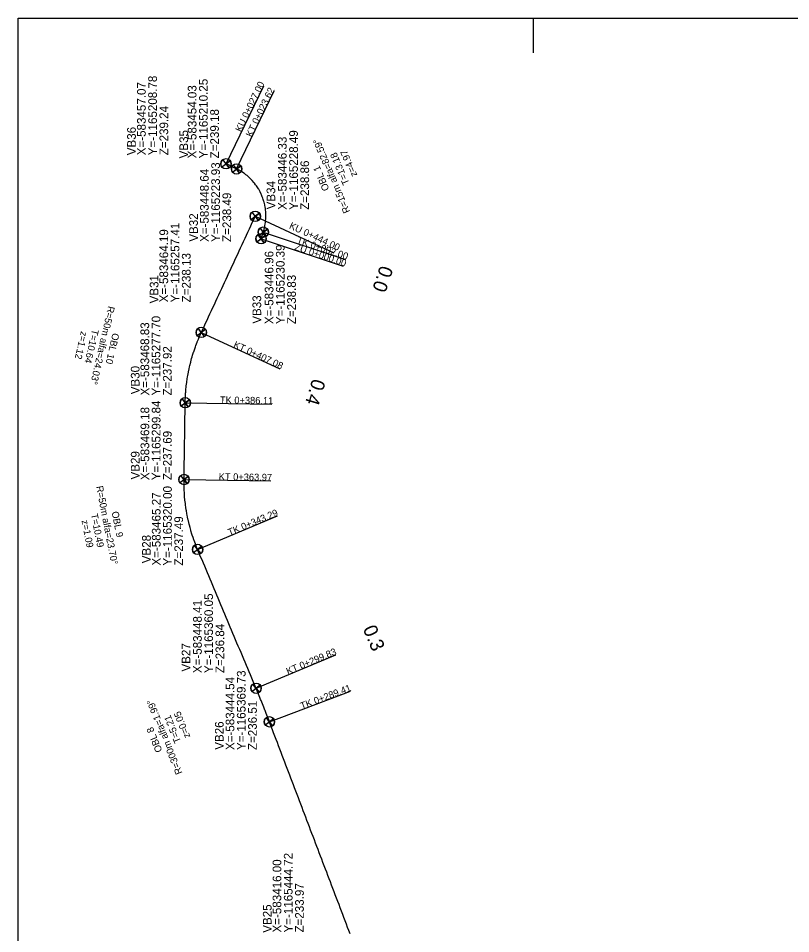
# Model space of a CAD drawing. Extents: x -583517 to -548566, y -1166112 to -1101582.
# Drawn here: x -583517 to -583294.2, y -1165430.8 to -1165166.8 of the extents above; entities that cross this region are included whole.
import ezdxf

# ---------------------------------------------------------------- set-up
doc = ezdxf.new("R2010")
doc.units = 0
for name, color, linetype in [('13', 7, 'Continuous'), ('56', 7, 'Continuous'), ('59', 7, 'Continuous'), ('8', 7, 'Continuous'), ('Body pricny rez', 7, 'Continuous'), ('Popis pricneho profilu', 7, 'Continuous')]:
    doc.layers.add(name, color=color, linetype=linetype)

msp = doc.modelspace()

# ---------------------------------------------------------------- linework, layer by layer
at = {"layer": '13'}
for points in [[(-583457.07, -1165208.78), (-583446.19, -1165186.27)], [(-583454.03, -1165210.25), (-583443.15, -1165187.75)], [(-583448.64, -1165223.93), (-583425.96, -1165234.46)], [(-583446.33, -1165228.49), (-583422.61, -1165236.38)], [(-583446.96, -1165230.39), (-583423.24, -1165238.28)], [(-583464.19, -1165257.41), (-583441.51, -1165267.94)], [(-583468.83, -1165277.7), (-583443.84, -1165278.09)], [(-583469.18, -1165299.84), (-583444.18, -1165300.22)], [(-583465.27, -1165320), (-583442.22, -1165310.3)], [(-583448.41, -1165360.05), (-583425.37, -1165350.36)], [(-583444.54, -1165369.73), (-583421.17, -1165360.84)]]:
    msp.add_lwpolyline(points, dxfattribs=at)
at = {"layer": '56'}
msp.add_lwpolyline([(-583446.96, -1165230.39), (-583446.65, -1165229.44), (-583446.33, -1165228.49), (-583446.1, -1165227.72), (-583446.05, -1165227.53), (-583445.91, -1165226.95), (-583445.83, -1165226.56), (-583445.76, -1165226.16), (-583445.68, -1165225.57), (-583445.65, -1165225.37), (-583445.59, -1165224.57), (-583445.59, -1165224.57), (-583445.57, -1165223.77), (-583445.57, -1165223.57), (-583445.59, -1165222.97), (-583445.61, -1165222.57), (-583445.65, -1165222.17), (-583445.72, -1165221.58), (-583445.76, -1165221.38), (-583445.9, -1165220.6), (-583445.9, -1165220.59), (-583446.09, -1165219.81), (-583446.14, -1165219.63), (-583446.32, -1165219.04), (-583446.45, -1165218.67), (-583446.6, -1165218.29), (-583446.82, -1165217.75), (-583446.91, -1165217.55), (-583447.25, -1165216.84), (-583447.26, -1165216.83), (-583447.65, -1165216.13), (-583447.74, -1165215.97), (-583448.07, -1165215.45), (-583448.29, -1165215.14), (-583448.53, -1165214.8), (-583448.89, -1165214.34), (-583449.03, -1165214.17), (-583449.54, -1165213.58), (-583449.56, -1165213.57), (-583450.11, -1165212.99), (-583450.25, -1165212.87), (-583450.7, -1165212.45), (-583450.99, -1165212.2), (-583451.32, -1165211.94), (-583451.78, -1165211.59), (-583451.96, -1165211.47), (-583452.61, -1165211.03), (-583452.63, -1165211.02), (-583453.32, -1165210.62), (-583453.48, -1165210.53), (-583454.03, -1165210.25), (-583454.37, -1165210.09), (-583455.27, -1165209.65), (-583456.17, -1165209.22), (-583457.07, -1165208.78)], dxfattribs=at)
at = {"layer": '8'}
for p, q in [((-583458.28, -1165209.67), (-583455.87, -1165207.89)), ((-583456.18, -1165209.98), (-583457.97, -1165207.58)), ((-583457.07, -1165208.78), (-583457.97, -1165207.58)), ((-583455.87, -1165207.88), (-583457.07, -1165208.78)), ((-583455.87, -1165207.88), (-583457.07, -1165208.78)), ((-583458.28, -1165209.68), (-583457.07, -1165208.78)), ((-583457.07, -1165208.78), (-583456.18, -1165209.98)), ((-583457.07, -1165208.78), (-583456.18, -1165209.98)), ((-583455.24, -1165211.15), (-583452.83, -1165209.36)), ((-583455.24, -1165211.15), (-583454.03, -1165210.25)), ((-583453.14, -1165211.45), (-583454.93, -1165209.05)), ((-583454.03, -1165210.25), (-583454.93, -1165209.05)), ((-583452.83, -1165209.36), (-583454.03, -1165210.25)), ((-583452.83, -1165209.36), (-583454.03, -1165210.25)), ((-583454.03, -1165210.25), (-583453.14, -1165211.45)), ((-583454.03, -1165210.25), (-583453.14, -1165211.45)), ((-583449.84, -1165224.82), (-583447.43, -1165223.03)), ((-583449.84, -1165224.82), (-583448.64, -1165223.93)), ((-583447.74, -1165225.13), (-583449.53, -1165222.72)), ((-583448.64, -1165223.93), (-583449.53, -1165222.72)), ((-583447.43, -1165223.03), (-583448.64, -1165223.93)), ((-583447.43, -1165223.03), (-583448.64, -1165223.93)), ((-583448.64, -1165223.93), (-583447.74, -1165225.13)), ((-583448.64, -1165223.93), (-583447.74, -1165225.13)), ((-583448.17, -1165231.28), (-583445.76, -1165229.49)), ((-583446.07, -1165231.59), (-583447.86, -1165229.18)), ((-583446.96, -1165230.39), (-583447.86, -1165229.18)), ((-583447.54, -1165229.38), (-583445.13, -1165227.6)), ((-583447.54, -1165229.39), (-583446.33, -1165228.49)), ((-583445.44, -1165229.69), (-583447.23, -1165227.29)), ((-583446.33, -1165228.49), (-583447.23, -1165227.29)), ((-583445.76, -1165229.49), (-583446.96, -1165230.39)), ((-583445.76, -1165229.49), (-583446.96, -1165230.39)), ((-583445.13, -1165227.59), (-583446.33, -1165228.49)), ((-583445.13, -1165227.59), (-583446.33, -1165228.49)), ((-583446.33, -1165228.49), (-583445.44, -1165229.69)), ((-583446.33, -1165228.49), (-583445.44, -1165229.69)), ((-583448.17, -1165231.28), (-583446.96, -1165230.39)), ((-583446.96, -1165230.39), (-583446.07, -1165231.59)), ((-583446.96, -1165230.39), (-583446.07, -1165231.59)), ((-583465.39, -1165258.31), (-583462.98, -1165256.52)), ((-583465.39, -1165258.31), (-583464.19, -1165257.41)), ((-583463.29, -1165258.62), (-583465.08, -1165256.21)), ((-583464.19, -1165257.41), (-583465.08, -1165256.21)), ((-583462.98, -1165256.52), (-583464.19, -1165257.41)), ((-583462.98, -1165256.52), (-583464.19, -1165257.41)), ((-583464.19, -1165257.41), (-583463.29, -1165258.62)), ((-583464.19, -1165257.41), (-583463.29, -1165258.62)), ((-583470.04, -1165278.6), (-583467.63, -1165276.81)), ((-583467.94, -1165278.91), (-583469.73, -1165276.5)), ((-583468.83, -1165277.7), (-583469.73, -1165276.5)), ((-583467.63, -1165276.81), (-583468.83, -1165277.7)), ((-583467.63, -1165276.81), (-583468.83, -1165277.7)), ((-583470.04, -1165278.6), (-583468.83, -1165277.7)), ((-583468.83, -1165277.7), (-583467.94, -1165278.91)), ((-583468.83, -1165277.7), (-583467.94, -1165278.91)), ((-583470.38, -1165300.73), (-583467.97, -1165298.94)), ((-583470.38, -1165300.73), (-583469.18, -1165299.84)), ((-583468.28, -1165301.04), (-583470.07, -1165298.63)), ((-583469.18, -1165299.84), (-583470.07, -1165298.63)), ((-583467.97, -1165298.94), (-583469.18, -1165299.84)), ((-583467.97, -1165298.94), (-583469.18, -1165299.84)), ((-583469.18, -1165299.84), (-583468.28, -1165301.04)), ((-583469.18, -1165299.84), (-583468.28, -1165301.04)), ((-583466.47, -1165320.89), (-583464.06, -1165319.1)), ((-583464.37, -1165321.2), (-583466.16, -1165318.8)), ((-583465.27, -1165320), (-583466.16, -1165318.8)), ((-583464.06, -1165319.1), (-583465.27, -1165320)), ((-583464.06, -1165319.1), (-583465.27, -1165320)), ((-583466.47, -1165320.89), (-583465.27, -1165320)), ((-583465.27, -1165320), (-583464.37, -1165321.2)), ((-583465.27, -1165320), (-583464.37, -1165321.2)), ((-583447.52, -1165361.26), (-583449.31, -1165358.85)), ((-583448.41, -1165360.05), (-583449.31, -1165358.85)), ((-583449.62, -1165360.95), (-583447.21, -1165359.16)), ((-583449.62, -1165360.95), (-583448.41, -1165360.05)), ((-583447.21, -1165359.16), (-583448.41, -1165360.05)), ((-583447.21, -1165359.16), (-583448.41, -1165360.05)), ((-583448.41, -1165360.05), (-583447.52, -1165361.26)), ((-583448.41, -1165360.05), (-583447.52, -1165361.26)), ((-583445.74, -1165370.63), (-583443.33, -1165368.84)), ((-583443.64, -1165370.93), (-583445.43, -1165368.53)), ((-583444.54, -1165369.73), (-583445.43, -1165368.53)), ((-583443.33, -1165368.84), (-583444.54, -1165369.73)), ((-583443.33, -1165368.84), (-583444.54, -1165369.73)), ((-583445.74, -1165370.63), (-583444.54, -1165369.73)), ((-583444.54, -1165369.73), (-583443.64, -1165370.94)), ((-583444.54, -1165369.73), (-583443.64, -1165370.94))]:
    msp.add_line(p, q, dxfattribs=at)
for centre in [(-583457.07, -1165208.78), (-583454.03, -1165210.25), (-583448.64, -1165223.93), (-583446.33, -1165228.49), (-583446.96, -1165230.39), (-583464.19, -1165257.41), (-583468.83, -1165277.7), (-583469.18, -1165299.84), (-583465.27, -1165320), (-583448.41, -1165360.05), (-583444.54, -1165369.73)]:
    msp.add_circle(centre, 1.5, dxfattribs=at)
for centre, start, end in [((-583457.07, -1165208.78), 126.6271, 216.6271), ((-583457.07, -1165208.78), 306.6271, 36.6271), ((-583457.07, -1165208.78), 306.6271, 36.6271), ((-583454.03, -1165210.25), 126.6271, 216.6271), ((-583454.03, -1165210.25), 306.6271, 36.6271), ((-583454.03, -1165210.25), 306.6271, 36.6271), ((-583448.64, -1165223.93), 126.6271, 216.6271), ((-583448.64, -1165223.93), 306.6271, 36.6271), ((-583448.64, -1165223.93), 306.6271, 36.6271), ((-583446.96, -1165230.39), 126.6271, 216.6271), ((-583446.33, -1165228.49), 126.6271, 216.6271), ((-583446.96, -1165230.39), 306.6271, 36.6271), ((-583446.96, -1165230.39), 306.6271, 36.6271), ((-583446.33, -1165228.49), 306.6271, 36.6271), ((-583446.33, -1165228.49), 306.6271, 36.6271), ((-583464.19, -1165257.41), 126.6271, 216.6271), ((-583464.19, -1165257.41), 306.6271, 36.6271), ((-583464.19, -1165257.41), 306.6271, 36.6271), ((-583468.83, -1165277.7), 126.6271, 216.6271), ((-583468.83, -1165277.7), 306.6271, 36.6271), ((-583468.83, -1165277.7), 306.6271, 36.6271), ((-583469.18, -1165299.84), 126.6271, 216.6271), ((-583469.18, -1165299.84), 306.6271, 36.6271), ((-583469.18, -1165299.84), 306.6271, 36.6271), ((-583465.27, -1165320), 126.6271, 216.6271), ((-583465.27, -1165320), 306.6271, 36.6271), ((-583465.27, -1165320), 306.6271, 36.6271), ((-583448.41, -1165360.05), 126.6271, 216.6271), ((-583448.41, -1165360.05), 306.6271, 36.6271), ((-583448.41, -1165360.05), 306.6271, 36.6271), ((-583444.54, -1165369.73), 126.6271, 216.6271), ((-583444.54, -1165369.73), 306.6271, 36.6271), ((-583444.54, -1165369.73), 306.6271, 36.6271)]:
    msp.add_arc(centre, 1.5, start, end, dxfattribs=at)
at = {"layer": 'Body pricny rez'}
msp.add_lwpolyline([(-583421.28, -1165430.86), (-583421.63, -1165429.93), (-583421.99, -1165428.99), (-583422.35, -1165428.06), (-583422.7, -1165427.12), (-583423.06, -1165426.19), (-583423.41, -1165425.25), (-583423.77, -1165424.32), (-583424.12, -1165423.38), (-583424.48, -1165422.45), (-583424.83, -1165421.52), (-583425.19, -1165420.58), (-583425.55, -1165419.65), (-583425.9, -1165418.71), (-583426.26, -1165417.78), (-583426.61, -1165416.84), (-583426.97, -1165415.91), (-583427.32, -1165414.97), (-583427.68, -1165414.04), (-583428.04, -1165413.1), (-583428.39, -1165412.17), (-583428.75, -1165411.23), (-583429.1, -1165410.3), (-583429.46, -1165409.37), (-583429.81, -1165408.43), (-583430.17, -1165407.5), (-583430.52, -1165406.56), (-583430.88, -1165405.63), (-583431.24, -1165404.69), (-583431.59, -1165403.76), (-583431.95, -1165402.82), (-583432.3, -1165401.89), (-583432.66, -1165400.95), (-583433.01, -1165400.02), (-583433.37, -1165399.08), (-583433.72, -1165398.15), (-583434.08, -1165397.21), (-583434.44, -1165396.28), (-583434.79, -1165395.35), (-583435.15, -1165394.41), (-583435.5, -1165393.48), (-583435.86, -1165392.54), (-583436.21, -1165391.61), (-583436.57, -1165390.67), (-583436.93, -1165389.74), (-583437.28, -1165388.8), (-583437.64, -1165387.87), (-583437.99, -1165386.93), (-583438.35, -1165386), (-583438.7, -1165385.06), (-583439.06, -1165384.13), (-583439.41, -1165383.2), (-583439.77, -1165382.26), (-583440.13, -1165381.33), (-583440.48, -1165380.39), (-583440.84, -1165379.46), (-583441.19, -1165378.52), (-583441.55, -1165377.59), (-583441.9, -1165376.65), (-583442.26, -1165375.72), (-583442.61, -1165374.78), (-583442.97, -1165373.85), (-583443.33, -1165372.91), (-583443.68, -1165371.98), (-583444.04, -1165371.04), (-583444.39, -1165370.11), (-583444.54, -1165369.73), (-583444.75, -1165369.18), (-583445.11, -1165368.24), (-583445.47, -1165367.31), (-583445.79, -1165366.49), (-583445.84, -1165366.38), (-583446.2, -1165365.45), (-583446.58, -1165364.52), (-583446.95, -1165363.59), (-583447.08, -1165363.26), (-583447.33, -1165362.67), (-583447.71, -1165361.74), (-583448.09, -1165360.82), (-583448.41, -1165360.05), (-583448.48, -1165359.9), (-583448.87, -1165358.98), (-583449.25, -1165358.05), (-583449.64, -1165357.13), (-583450.03, -1165356.21), (-583450.42, -1165355.29), (-583450.81, -1165354.37), (-583451.19, -1165353.45), (-583451.58, -1165352.52), (-583451.97, -1165351.6), (-583452.16, -1165351.14), (-583452.36, -1165350.68), (-583452.74, -1165349.76), (-583453.13, -1165348.84), (-583453.52, -1165347.92), (-583453.91, -1165346.99), (-583454.3, -1165346.07), (-583454.68, -1165345.15), (-583455.07, -1165344.23), (-583455.46, -1165343.31), (-583455.85, -1165342.39), (-583456.24, -1165341.46), (-583456.62, -1165340.54), (-583457.01, -1165339.62), (-583457.4, -1165338.7), (-583457.79, -1165337.78), (-583458.17, -1165336.85), (-583458.56, -1165335.93), (-583458.95, -1165335.01), (-583459.34, -1165334.09), (-583459.73, -1165333.17), (-583460.11, -1165332.25), (-583460.5, -1165331.32), (-583460.89, -1165330.4), (-583461.28, -1165329.48), (-583461.67, -1165328.56), (-583462.05, -1165327.64), (-583462.44, -1165326.72), (-583462.83, -1165325.79), (-583463.22, -1165324.87), (-583463.6, -1165323.95), (-583463.99, -1165323.03), (-583464.38, -1165322.11), (-583464.77, -1165321.19), (-583465.16, -1165320.26), (-583465.27, -1165320), (-583465.54, -1165319.34), (-583465.82, -1165318.63), (-583465.9, -1165318.41), (-583466.25, -1165317.47), (-583466.33, -1165317.24), (-583466.58, -1165316.53), (-583466.8, -1165315.84), (-583466.89, -1165315.58), (-583467.18, -1165314.62), (-583467.23, -1165314.43), (-583467.45, -1165313.66), (-583467.62, -1165313), (-583467.7, -1165312.69), (-583467.93, -1165311.72), (-583467.97, -1165311.57), (-583468.14, -1165310.74), (-583468.27, -1165310.12), (-583468.34, -1165309.76), (-583468.51, -1165308.77), (-583468.53, -1165308.67), (-583468.66, -1165307.78), (-583468.74, -1165307.2), (-583468.8, -1165306.79), (-583468.91, -1165305.8), (-583468.92, -1165305.74), (-583469.01, -1165304.8), (-583469.05, -1165304.27), (-583469.08, -1165303.81), (-583469.13, -1165302.81), (-583469.13, -1165302.79), (-583469.17, -1165301.81), (-583469.18, -1165301.31), (-583469.18, -1165300.81), (-583469.18, -1165299.84), (-583469.18, -1165299.81), (-583469.16, -1165298.81), (-583469.14, -1165297.81), (-583469.13, -1165296.81), (-583469.11, -1165295.81), (-583469.1, -1165294.81), (-583469.08, -1165293.81), (-583469.07, -1165292.81), (-583469.05, -1165291.81), (-583469.04, -1165290.81), (-583469.02, -1165289.81), (-583469.01, -1165288.81), (-583468.99, -1165287.81), (-583468.98, -1165286.81), (-583468.96, -1165285.81), (-583468.94, -1165284.81), (-583468.93, -1165283.81), (-583468.91, -1165282.81), (-583468.9, -1165281.81), (-583468.88, -1165280.81), (-583468.87, -1165279.81), (-583468.85, -1165278.81), (-583468.84, -1165277.81), (-583468.83, -1165277.7), (-583468.81, -1165276.81), (-583468.79, -1165276.21), (-583468.77, -1165275.81), (-583468.71, -1165274.81), (-583468.7, -1165274.71), (-583468.62, -1165273.82), (-583468.56, -1165273.22), (-583468.52, -1165272.82), (-583468.4, -1165271.83), (-583468.38, -1165271.73), (-583468.25, -1165270.84), (-583468.16, -1165270.25), (-583468.09, -1165269.85), (-583467.91, -1165268.87), (-583467.89, -1165268.78), (-583467.71, -1165267.89), (-583467.58, -1165267.31), (-583467.49, -1165266.92), (-583467.25, -1165265.95), (-583467.22, -1165265.86), (-583466.99, -1165264.98), (-583466.82, -1165264.42), (-583466.71, -1165264.02), (-583466.41, -1165263.07), (-583466.38, -1165262.98), (-583466.09, -1165262.12), (-583465.9, -1165261.57), (-583465.75, -1165261.18), (-583465.4, -1165260.24), (-583465.37, -1165260.17), (-583465.02, -1165259.31), (-583464.8, -1165258.78), (-583464.63, -1165258.39), (-583464.22, -1165257.48), (-583464.19, -1165257.41), (-583463.8, -1165256.58), (-583463.38, -1165255.67), (-583462.96, -1165254.76), (-583462.54, -1165253.86), (-583462.11, -1165252.95), (-583461.69, -1165252.04), (-583461.27, -1165251.13), (-583460.85, -1165250.23), (-583460.43, -1165249.32), (-583460.01, -1165248.41), (-583459.59, -1165247.51), (-583459.17, -1165246.6), (-583458.74, -1165245.69), (-583458.32, -1165244.79), (-583457.9, -1165243.88), (-583457.48, -1165242.97), (-583457.06, -1165242.06), (-583456.64, -1165241.16), (-583456.22, -1165240.25), (-583455.8, -1165239.34), (-583455.38, -1165238.44), (-583454.95, -1165237.53), (-583454.53, -1165236.62), (-583454.11, -1165235.72), (-583453.69, -1165234.81), (-583453.27, -1165233.9), (-583452.85, -1165233), (-583452.43, -1165232.09), (-583452.01, -1165231.18), (-583451.58, -1165230.27), (-583451.16, -1165229.37), (-583450.74, -1165228.46), (-583450.32, -1165227.55), (-583449.9, -1165226.65), (-583449.48, -1165225.74), (-583449.06, -1165224.83), (-583448.64, -1165223.93)], dxfattribs=at)
at = {"layer": 'Popis pricneho profilu'}
msp.add_line((-583368.47, -1165166.82), (-583368.47, -1165176.82), dxfattribs=at)
msp.add_lwpolyline([(-583516.97, -1166111.82), (-583516.97, -1165166.82), (-583071.47, -1165166.82), (-583071.47, -1166111.82)], close=True, dxfattribs=at)

# ---------------------------------------------------------------- texts
at = {"layer": '13'}
for s, height, rotation, p in [('KU 0+027.00', 2, 64.1872, (-583452.72, -1165199.78)), ('KT 0+023.62', 2, 64.1872, (-583449.68, -1165201.25)), ('R=15m alfa=82.59%%d', 2, 112.8908, (-583421.25, -1165222.55)), ('  T=13.18', 2, 112.8908, (-583420.86, -1165215.78)), ('   z=4.97', 2, 112.8908, (-583418.31, -1165214.11)), ('OBL 1', 2, 112.8908, (-583427.23, -1165216.11)), ('KU 0+444.00', 2, 335.0882, (-583439.02, -1165227.33)), ('ZU 0+000.00', 2, 341.5943, (-583437.48, -1165233.55)), ('TK 0+002.00', 2, 341.5943, (-583436.84, -1165231.65)), ('0.0', 4, 251.5943, (-583412.57, -1165237.88)), ('R=50m alfa=24.03%%d', 2, 257.1024, (-583491.06, -1165249.69)), ('   z=1.12', 2, 257.1024, (-583498.39, -1165254.82)), ('  T=10.64', 2, 257.1024, (-583495.34, -1165254.95)), ('OBL 10', 2, 257.1024, (-583489.76, -1165257.46)), ('KT 0+407.08', 2, 335.0882, (-583455.12, -1165261.63)), ('0.4', 4, 253.1975, (-583432.12, -1165270.55)), ('TK 0+386.11', 2, 359.1166, (-583458.84, -1165277.86)), ('KT 0+363.97', 2, 359.1166, (-583459.18, -1165299.99)), ('R=50m alfa=23.70%%d', 2, 280.969, (-583494.54, -1165301.86)), ('TK 0+343.29', 2, 22.8214, (-583456.05, -1165316.12)), ('   z=1.09', 2, 280.969, (-583499.17, -1165309.5)), ('  T=10.49', 2, 280.969, (-583496.33, -1165308.4)), ('OBL 9', 2, 280.969, (-583490.06, -1165309.2)), ('0.3', 4, 292.8214, (-583417.68, -1165342.86)), ('KT 0+299.83', 2, 22.8214, (-583439.2, -1165356.18)), ('TK 0+289.41', 2, 20.8304, (-583435.19, -1165366.18)), ('R=300m alfa=1.99%%d', 2, 111.8259, (-583469.61, -1165384.44)), ('   z=0.05', 2, 111.8259, (-583466.5, -1165376.06)), ('  T=5.21', 2, 111.8259, (-583469.45, -1165376.77)), ('OBL 8', 2, 111.8259, (-583475.4, -1165378.07))]:
    msp.add_text(s, height=height, rotation=rotation, dxfattribs=at).set_placement(p)
at = {"layer": '59'}
for s, p in [('Y=-1165208.78', (-583476.99, -1165206.32)), ('Y=-1165210.25', (-583462.35, -1165207.22)), ('X=-583457.07', (-583480.22, -1165206.32)), ('X=-583454.03', (-583465.59, -1165207.22)), ('Z=239.24', (-583473.75, -1165206.32)), ('Z=239.18', (-583459.12, -1165207.22)), ('VB36', (-583483.08, -1165206.31)), ('VB35', (-583468.01, -1165207.22)), ('Y=-1165228.49', (-583436.34, -1165222.06)), ('X=-583446.33', (-583439.58, -1165222.06)), ('Y=-1165223.93', (-583458.82, -1165231.32)), ('Z=238.86', (-583433.11, -1165222.06)), ('X=-583448.64', (-583462.06, -1165231.32)), ('VB34', (-583442.87, -1165221.92)), ('Z=238.49', (-583455.59, -1165231.32)), ('VB32', (-583465.18, -1165231.24)), ('Y=-1165257.41', (-583470.52, -1165248.74)), ('X=-583464.19', (-583473.76, -1165248.74)), ('Y=-1165230.39', (-583440.17, -1165255.02)), ('Z=238.13', (-583467.29, -1165248.74)), ('X=-583446.96', (-583443.4, -1165255.02)), ('VB31', (-583476.56, -1165249.04)), ('Z=238.83', (-583436.93, -1165255.02)), ('VB33', (-583446.93, -1165254.89)), ('Y=-1165277.70', (-583476, -1165275.6)), ('X=-583468.83', (-583479.23, -1165275.6)), ('Z=237.92', (-583472.76, -1165275.6)), ('VB30', (-583482.01, -1165275.25)), ('Y=-1165299.84', (-583475.97, -1165300.02)), ('X=-583469.18', (-583479.21, -1165300.02)), ('Z=237.69', (-583472.74, -1165300.02)), ('VB29', (-583482.01, -1165299.82)), ('Y=-1165320.00', (-583472.71, -1165324.66)), ('X=-583465.27', (-583475.94, -1165324.66)), ('Z=237.49', (-583469.47, -1165324.66)), ('VB28', (-583478.77, -1165323.99)), ('X=-583448.41', (-583464.06, -1165355.67)), ('Y=-1165360.05', (-583460.83, -1165355.67)), ('Z=236.84', (-583457.59, -1165355.67)), ('VB27', (-583467.35, -1165355.22)), ('Y=-1165369.73', (-583451.43, -1165377.86)), ('X=-583444.54', (-583454.66, -1165377.86)), ('Z=236.51', (-583448.19, -1165377.86)), ('VB26', (-583457.76, -1165377.77)), ('Y=-1165444.72', (-583437.88, -1165430.48)), ('X=-583416.00', (-583441.12, -1165430.48)), ('Z=233.97', (-583434.64, -1165430.48)), ('VB25', (-583443.93, -1165430.55))]:
    msp.add_text(s, height=2.5, rotation=90, dxfattribs=at).set_placement(p)

doc.saveas('drawing.dxf')
